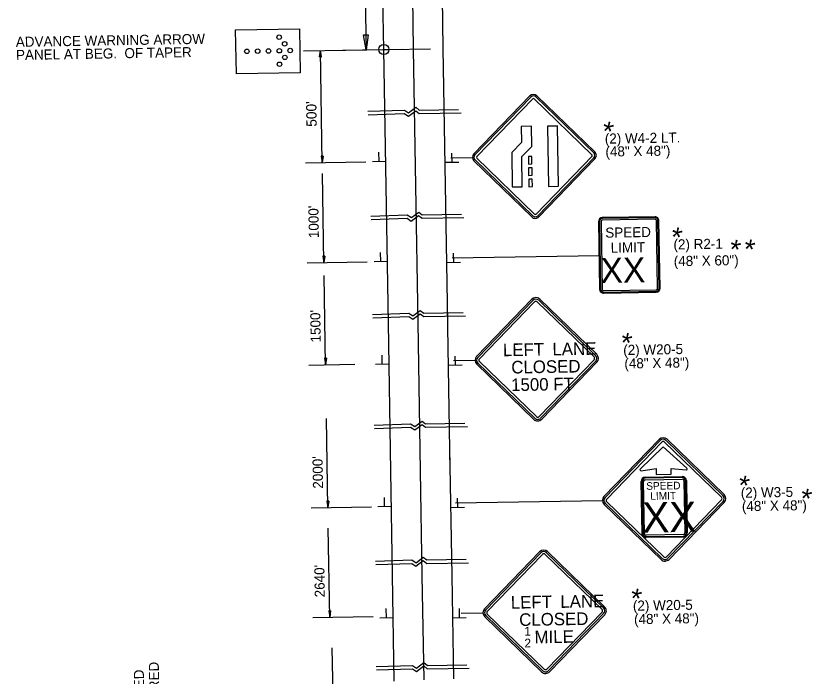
# Model space of a CAD drawing. Extents: x 1676063 to 1678026, y 228339 to 229904.
# Drawn here: x 1676063.3 to 1676538, y 228722.5 to 229116.1 of the extents above; entities that cross this region are included whole.
import ezdxf

# ---------------------------------------------------------------- set-up
doc = ezdxf.new("R2010")
doc.units = 0
for name, color, linetype in [('Default', 7, 'Continuous'), ('P_TC_Signs_Permanent', 7, 'Continuous'), ('P_TC_Signs_Temporary', 7, 'Continuous'), ('R_Annotation', 7, 'Continuous')]:
    doc.layers.add(name, color=color, linetype=linetype)

msp = doc.modelspace()

# ---------------------------------------------------------------- linework, layer by layer
at = {"layer": 'Default'}
for p, q in [((1676300.39, 229096.37), (1676288.34, 229823.3)), ((1676318.12, 229096.67), (1676306.07, 229823.59)), ((1676282.66, 229096.08), (1676270.61, 229823.01)), ((1676264.41, 229556.88), (1676272.05, 229095.9)), ((1676270.58, 229104.75), (1676273.23, 229104.79)), ((1676272.05, 229095.9), (1676270.58, 229104.75)), ((1676273.23, 229104.79), (1676272.05, 229095.9)), ((1676234.82, 229095.29), (1676310.43, 229096.54)), ((1676244.3, 229091.62), (1676244.81, 229095.45)), ((1676244.39, 229091.62), (1676244.82, 229094.81)), ((1676244.49, 229091.62), (1676244.83, 229094.16)), ((1676244.58, 229091.62), (1676244.84, 229093.52)), ((1676244.68, 229091.63), (1676244.85, 229092.87)), ((1676244.78, 229091.63), (1676244.86, 229092.23)), ((1676245.91, 229028.68), (1676244.81, 229095.45)), ((1676245.44, 229091.64), (1676244.81, 229095.45)), ((1676245.35, 229091.64), (1676244.82, 229094.81)), ((1676245.25, 229091.63), (1676244.83, 229094.16)), ((1676245.15, 229091.63), (1676244.84, 229093.52)), ((1676245.06, 229091.63), (1676244.85, 229092.87)), ((1676244.96, 229091.63), (1676244.86, 229092.23)), ((1676258.1, 229095.67), (1676294.01, 229096.27)), ((1676285.36, 228932.99), (1676282.66, 229096.08)), ((1676303.09, 228933.28), (1676300.39, 229096.37)), ((1676320.82, 228933.58), (1676318.12, 229096.67)), ((1676244.3, 229091.62), (1676245.44, 229091.64)), ((1676246.42, 229032.52), (1676245.28, 229032.5)), ((1676245.28, 229032.5), (1676245.91, 229028.68)), ((1676245.37, 229032.5), (1676245.9, 229029.32)), ((1676245.47, 229032.5), (1676245.89, 229029.98)), ((1676245.56, 229032.5), (1676245.88, 229030.61)), ((1676245.66, 229032.5), (1676245.87, 229031.26)), ((1676245.76, 229032.5), (1676245.86, 229031.9)), ((1676245.94, 229032.51), (1676245.86, 229031.9)), ((1676246.03, 229032.51), (1676245.87, 229031.26)), ((1676246.13, 229032.51), (1676245.88, 229030.61)), ((1676246.23, 229032.51), (1676245.89, 229029.98)), ((1676246.33, 229032.51), (1676245.9, 229029.32)), ((1676246.42, 229032.52), (1676245.91, 229028.68)), ((1676279.84, 229029.36), (1676279.75, 229034.81)), ((1676323.36, 229028.79), (1676323.26, 229034.24)), ((1676235.93, 229028.52), (1676271.84, 229029.11)), ((1676283.81, 229029.31), (1676275.83, 229029.18)), ((1676327.32, 229028.74), (1676319.35, 229028.61)), ((1676246.9, 228969.01), (1676246.02, 229022.23)), ((1676280.83, 228969.69), (1676280.74, 228975.13)), ((1676324.34, 228969.12), (1676324.25, 228974.57)), ((1676236.92, 228968.84), (1676272.82, 228969.44)), ((1676247.41, 228972.84), (1676246.26, 228972.82)), ((1676246.26, 228972.82), (1676246.9, 228969.01)), ((1676246.36, 228972.82), (1676246.89, 228969.65)), ((1676246.46, 228972.83), (1676246.88, 228970.3)), ((1676246.55, 228972.83), (1676246.87, 228970.94)), ((1676246.65, 228972.83), (1676246.86, 228971.59)), ((1676246.75, 228972.83), (1676246.85, 228972.23)), ((1676246.93, 228972.83), (1676246.85, 228972.23)), ((1676247.02, 228972.84), (1676246.86, 228971.59)), ((1676247.12, 228972.84), (1676246.87, 228970.94)), ((1676247.22, 228972.84), (1676246.88, 228970.3)), ((1676247.32, 228972.84), (1676246.89, 228969.65)), ((1676247.41, 228972.84), (1676246.9, 228969.01)), ((1676284.8, 228969.64), (1676276.82, 228969.5)), ((1676328.31, 228969.07), (1676320.34, 228968.94)), ((1676247.91, 228908.13), (1676247.03, 228961.36)), ((1676322.29, 228845.25), (1676320.67, 228942.93)), ((1676286.83, 228844.66), (1676285.36, 228932.99)), ((1676304.56, 228844.96), (1676303.09, 228933.28)), ((1676248.42, 228911.97), (1676247.27, 228911.95)), ((1676247.27, 228911.95), (1676247.91, 228908.13)), ((1676247.37, 228911.95), (1676247.9, 228908.77)), ((1676247.47, 228911.95), (1676247.89, 228909.43)), ((1676247.56, 228911.95), (1676247.88, 228910.07)), ((1676247.66, 228911.95), (1676247.87, 228910.71)), ((1676247.76, 228911.95), (1676247.86, 228911.35)), ((1676247.94, 228911.96), (1676247.86, 228911.35)), ((1676248.03, 228911.96), (1676247.87, 228910.71)), ((1676248.13, 228911.96), (1676247.88, 228910.07)), ((1676248.23, 228911.96), (1676247.89, 228909.43)), ((1676248.33, 228911.96), (1676247.9, 228908.77)), ((1676248.42, 228911.97), (1676247.91, 228908.13)), ((1676281.72, 228908.42), (1676281.63, 228913.87)), ((1676325.36, 228907.86), (1676325.27, 228913.3)), ((1676237.93, 228907.97), (1676265.31, 228908.42)), ((1676285.69, 228908.37), (1676277.71, 228908.24)), ((1676329.33, 228907.8), (1676321.35, 228907.67)), ((1676249.32, 228822.95), (1676248.44, 228876.17)), ((1676323.33, 228782.51), (1676322.07, 228858.33)), ((1676287.86, 228782.61), (1676286.83, 228844.66)), ((1676305.59, 228782.56), (1676304.56, 228844.96)), ((1676249.83, 228826.78), (1676248.69, 228826.76)), ((1676248.69, 228826.76), (1676249.32, 228822.95)), ((1676248.78, 228826.77), (1676249.31, 228823.59)), ((1676248.88, 228826.77), (1676249.3, 228824.25)), ((1676248.97, 228826.77), (1676249.29, 228824.88)), ((1676249.07, 228826.77), (1676249.28, 228825.53)), ((1676249.17, 228826.77), (1676249.27, 228826.17)), ((1676249.35, 228826.78), (1676249.27, 228826.17)), ((1676249.45, 228826.78), (1676249.28, 228825.53)), ((1676249.54, 228826.78), (1676249.29, 228824.88)), ((1676249.64, 228826.78), (1676249.3, 228824.25)), ((1676249.74, 228826.78), (1676249.31, 228823.59)), ((1676249.83, 228826.78), (1676249.32, 228822.95)), ((1676283.12, 228823.63), (1676283.03, 228829.07)), ((1676326.77, 228823.06), (1676326.68, 228828.51)), ((1676239.34, 228822.78), (1676275.25, 228823.38)), ((1676287.09, 228823.58), (1676279.11, 228823.44)), ((1676330.74, 228823.01), (1676322.76, 228822.88)), ((1676250.41, 228757.52), (1676249.53, 228810.74)), ((1676288.9, 228719.41), (1676287.86, 228782.61)), ((1676306.63, 228720.17), (1676305.59, 228782.56)), ((1676324.35, 228720.93), (1676323.33, 228782.51)), ((1676250.92, 228761.35), (1676249.77, 228761.33)), ((1676249.77, 228761.33), (1676250.41, 228757.52)), ((1676249.87, 228761.33), (1676250.4, 228758.15)), ((1676249.96, 228761.33), (1676250.39, 228758.81)), ((1676250.06, 228761.34), (1676250.38, 228759.45)), ((1676250.16, 228761.34), (1676250.37, 228760.1)), ((1676250.25, 228761.34), (1676250.35, 228760.74)), ((1676250.43, 228761.34), (1676250.35, 228760.74)), ((1676250.53, 228761.34), (1676250.37, 228760.1)), ((1676250.63, 228761.35), (1676250.38, 228759.45)), ((1676250.73, 228761.35), (1676250.39, 228758.81)), ((1676250.82, 228761.35), (1676250.4, 228758.15)), ((1676250.92, 228761.35), (1676250.41, 228757.52)), ((1676284.22, 228757.26), (1676284.13, 228762.71)), ((1676327.86, 228757.3), (1676327.77, 228762.74)), ((1676240.42, 228757.35), (1676276.33, 228757.95)), ((1676288.19, 228757.21), (1676280.21, 228757.08)), ((1676331.83, 228757.25), (1676323.85, 228757.11)), ((1676252.81, 228686.18), (1676251.93, 228739.41))]:
    msp.add_line(p, q, dxfattribs=at)
msp.add_lwpolyline([(1676232.72, 229082.1), (1676194.74, 229081.47), (1676194.31, 229107.74), (1676232.29, 229108.37)], close=True, dxfattribs=at)
for points in [[(1676273.17, 229059.22), (1676294.9, 229059.91), (1676297.39, 229058.3), (1676301.75, 229061.6), (1676303.82, 229059.93), (1676327.24, 229060.32)], [(1676273.4, 229057.19), (1676294.85, 229057.88), (1676297.34, 229056.26), (1676301.7, 229059.56), (1676303.77, 229057.9), (1676328.71, 229058.3)], [(1676274.85, 228996.77), (1676296.58, 228997.46), (1676299.07, 228995.85), (1676303.43, 228999.15), (1676305.5, 228997.48), (1676328.92, 228997.87)], [(1676275.08, 228994.74), (1676296.53, 228995.42), (1676299.02, 228993.81), (1676303.38, 228997.11), (1676305.45, 228995.44), (1676330.39, 228995.85)], [(1676275.82, 228938.17), (1676297.55, 228938.86), (1676300.04, 228937.25), (1676304.4, 228940.55), (1676306.47, 228938.88), (1676329.89, 228939.27)], [(1676276.05, 228936.14), (1676297.5, 228936.82), (1676299.99, 228935.21), (1676304.35, 228938.51), (1676306.42, 228936.84), (1676331.36, 228937.25)], [(1676276.92, 228872.18), (1676298.64, 228872.87), (1676301.13, 228871.26), (1676305.5, 228874.56), (1676307.56, 228872.89), (1676330.99, 228873.28)], [(1676277.15, 228870.15), (1676298.59, 228870.84), (1676301.08, 228869.22), (1676305.45, 228872.52), (1676307.51, 228870.86), (1676332.45, 228871.26)], [(1676277.62, 228791.03), (1676299.35, 228791.72), (1676301.84, 228790.1), (1676306.2, 228793.4), (1676308.27, 228791.74), (1676331.69, 228792.12)], [(1676277.85, 228789), (1676299.29, 228789.68), (1676301.79, 228788.07), (1676306.15, 228791.37), (1676308.21, 228789.7), (1676333.16, 228790.11)], [(1676277.99, 228728.19), (1676299.72, 228728.88), (1676302.21, 228727.26), (1676306.57, 228730.56), (1676308.64, 228728.9), (1676332.06, 228729.28)], [(1676278.22, 228726.16), (1676299.67, 228726.84), (1676302.16, 228725.22), (1676306.52, 228728.52), (1676308.59, 228726.86), (1676333.53, 228727.27)]]:
    msp.add_lwpolyline(points, dxfattribs=at)
for centre, radius in [((1676220.23, 229103.38), 1.34), ((1676223.52, 229099.41), 1.34), ((1676282.66, 229096.08), 3), ((1676201.01, 229095.01), 1.34), ((1676207.46, 229095.12), 1.34), ((1676213.91, 229095.22), 1.34), ((1676220.36, 229095.33), 1.34), ((1676223.65, 229091.36), 1.34), ((1676226.81, 229095.44), 1.34), ((1676220.49, 229087.28), 1.34)]:
    msp.add_circle(centre, radius, dxfattribs=at)
at = {"layer": 'P_TC_Signs_Permanent'}
for p, q in [((1676369.7, 229068.35), (1676336.33, 229033.85)), ((1676380.16, 229050.46), (1676386.16, 229050.56)), ((1676375.14, 228996.31), (1676408.51, 229030.81)), ((1676336.4, 229029.61), (1676370.9, 228996.24)), ((1676410.65, 228993.53), (1676411.32, 228953.03)), ((1676411.21, 228993.54), (1676411.88, 228953.04)), ((1676412.15, 228993.55), (1676412.82, 228953.06)), ((1676444.36, 228996.34), (1676412.86, 228995.82)), ((1676444.37, 228995.78), (1676412.87, 228995.25)), ((1676444.38, 228994.84), (1676412.89, 228994.32)), ((1676445.82, 228953.61), (1676445.15, 228994.1)), ((1676446.75, 228953.62), (1676446.08, 228994.12)), ((1676447.32, 228953.63), (1676446.65, 228994.13)), ((1676413.58, 228952.32), (1676445.08, 228952.84)), ((1676413.6, 228951.38), (1676445.1, 228951.91)), ((1676413.61, 228950.82), (1676445.1, 228951.34)), ((1676446.78, 228863.58), (1676413.93, 228829.62)), ((1676447.45, 228862.93), (1676414.6, 228828.97)), ((1676448.4, 228862.01), (1676415.54, 228828.05)), ((1676483.95, 228829.19), (1676449.99, 228862.04)), ((1676484.86, 228830.13), (1676450.9, 228862.98)), ((1676485.51, 228830.8), (1676451.55, 228863.66)), ((1676438.44, 228841.05), (1676460.63, 228841.41)), ((1676436.59, 228807.41), (1676436.08, 228838.61)), ((1676463.07, 228839.05), (1676463.59, 228807.86)), ((1676415.57, 228826.46), (1676449.53, 228793.61)), ((1676451.12, 228793.64), (1676483.97, 228827.6)), ((1676452.06, 228792.72), (1676484.92, 228826.68)), ((1676414.01, 228824.84), (1676447.97, 228791.99)), ((1676414.66, 228825.52), (1676448.62, 228792.67)), ((1676452.74, 228792.07), (1676485.59, 228826.03)), ((1676461.23, 228805.42), (1676439.03, 228805.05))]:
    msp.add_line(p, q, dxfattribs=at)
for points in [[(1676408.44, 229035.05), (1676391.19, 229051.74), (1676373.94, 229068.42)], [(1676336.97, 229033.23), (1676370.35, 229067.73)], [(1676371.43, 229066.68), (1676338.05, 229032.19)], [(1676406.77, 229033.32), (1676372.27, 229066.7)], [(1676373.32, 229067.78), (1676407.82, 229034.4)], [(1676338.07, 229031.34), (1676372.56, 228997.96)], [(1676373.41, 228997.98), (1676406.79, 229032.48)], [(1676407.86, 229031.43), (1676374.49, 228996.93)], [(1676371.52, 228996.88), (1676337.02, 229030.26)], [(1676463.3, 228846.37), (1676449.2, 228859.23), (1676435.54, 228845.91)], [(1676436.01, 228844.95), (1676444.95, 228846.22), (1676445.01, 228842.65), (1676454.01, 228842.8), (1676453.95, 228846.36), (1676462.86, 228845.4)], [(1676460.64, 228840.81), (1676449.55, 228840.63), (1676438.45, 228840.45)], [(1676436.68, 228838.62), (1676437.19, 228807.42)], [(1676438.09, 228807.44), (1676437.58, 228838.63)], [(1676438.46, 228839.55), (1676449.56, 228839.73), (1676460.66, 228839.91)], [(1676461.57, 228839.03), (1676462.09, 228807.83)], [(1676462.99, 228807.85), (1676462.47, 228839.04)], [(1676461.21, 228806.92), (1676439.01, 228806.55)], [(1676439.02, 228805.65), (1676461.22, 228806.02)]]:
    msp.add_lwpolyline(points, dxfattribs=at)
for points in [[(1676359.22, 229014.11), (1676365.22, 229014.21), (1676364.92, 229032.21), (1676370.82, 229038.3), (1676370.62, 229050.3), (1676364.62, 229050.2), (1676364.78, 229040.69), (1676358.88, 229034.59)], [(1676380.76, 229014.47), (1676386.76, 229014.57), (1676386.16, 229050.56), (1676380.16, 229050.46)], [(1676368.89, 229027.77), (1676370.99, 229027.81), (1676370.92, 229032.31), (1676368.82, 229032.27)], [(1676369.01, 229021.02), (1676371.11, 229021.06), (1676371.03, 229025.56), (1676368.93, 229025.52)], [(1676369.12, 229014.27), (1676371.22, 229014.31), (1676371.14, 229018.81), (1676369.04, 229018.77)]]:
    msp.add_lwpolyline(points, close=True, dxfattribs=at)
for centre, radius, start, end in [((1676371.86, 229066.27), 3, 45.9497, 135.9497), ((1676371.86, 229066.27), 2.1, 45.9497, 135.9497), ((1676371.86, 229066.27), 0.6, 45.9497, 135.9497), ((1676338.48, 229031.77), 3, 135.9497, 225.9497), ((1676338.48, 229031.77), 2.1, 135.9497, 225.9497), ((1676338.48, 229031.77), 0.6, 135.9497, 225.9497), ((1676406.36, 229032.89), 0.6, 315.9497, 45.9497), ((1676406.36, 229032.89), 2.1, 315.9497, 45.9497), ((1676406.36, 229032.89), 3, 315.9497, 45.9497), ((1676372.98, 228998.39), 0.6, 225.9497, 315.9497), ((1676372.98, 228998.39), 3, 225.9497, 315.9497), ((1676372.98, 228998.39), 2.1, 225.9497, 315.9497), ((1676412.9, 228993.57), 2.25, 90.9497, 180.9497), ((1676412.9, 228993.57), 1.69, 90.9497, 180.9497), ((1676412.9, 228993.57), 0.75, 90.9497, 180.9497), ((1676444.4, 228994.09), 2.25, 0.9497, 90.9497), ((1676444.4, 228994.09), 1.69, 0.9497, 90.9497), ((1676444.4, 228994.09), 0.75, 0.9497, 90.9497), ((1676413.57, 228953.07), 2.25, 180.9497, 270.9497), ((1676413.57, 228953.07), 1.69, 180.9497, 270.9497), ((1676413.57, 228953.07), 0.75, 180.9497, 270.9497), ((1676445.07, 228953.59), 0.75, 270.9497, 0.9497), ((1676445.07, 228953.59), 2.25, 270.9497, 0.9497), ((1676445.07, 228953.59), 1.69, 270.9497, 0.9497), ((1676449.2, 228861.23), 3.38, 45.9497, 135.9497), ((1676449.2, 228861.23), 2.44, 45.9497, 135.9497), ((1676449.2, 228861.23), 1.13, 45.9497, 135.9497), ((1676435.93, 228845.51), 0.563, 134.2614, 278.0747), ((1676462.92, 228845.96), 0.563, 263.8247, 47.6381), ((1676438.48, 228838.65), 2.4, 90.9497, 180.9497), ((1676460.67, 228839.01), 2.4, 0.9497, 90.9497), ((1676460.67, 228839.01), 1.8, 0.9497, 90.9497), ((1676438.48, 228838.65), 1.8, 90.9497, 180.9497), ((1676438.48, 228838.65), 0.9, 90.9497, 180.9497), ((1676460.67, 228839.01), 0.9, 0.9497, 90.9497), ((1676416.35, 228827.27), 3.38, 135.9497, 225.9497), ((1676416.35, 228827.27), 2.44, 135.9497, 225.9497), ((1676416.35, 228827.27), 1.13, 135.9497, 225.9497), ((1676483.16, 228828.38), 1.13, 315.9497, 45.9497), ((1676483.16, 228828.38), 2.44, 315.9497, 45.9497), ((1676483.16, 228828.38), 3.38, 315.9497, 45.9497), ((1676438.99, 228807.45), 2.4, 180.9497, 270.9497), ((1676438.99, 228807.45), 1.8, 180.9497, 270.9497), ((1676438.99, 228807.45), 0.9, 180.9497, 270.9497), ((1676461.19, 228807.82), 0.9, 270.9497, 0.9497), ((1676461.19, 228807.82), 1.8, 270.9497, 0.9497), ((1676461.19, 228807.82), 2.4, 270.9497, 0.9497), ((1676450.31, 228794.42), 1.13, 225.9497, 315.9497), ((1676450.31, 228794.42), 3.38, 225.9497, 315.9497), ((1676450.31, 228794.42), 2.44, 225.9497, 315.9497)]:
    msp.add_arc(centre, radius, start, end, dxfattribs=at)
at = {"layer": 'P_TC_Signs_Temporary'}
for p, q in [((1676338.01, 228913.18), (1676370.86, 228947.14)), ((1676338.68, 228912.52), (1676371.53, 228946.48)), ((1676339.62, 228911.61), (1676372.48, 228945.57)), ((1676374.07, 228945.6), (1676408.03, 228912.75)), ((1676374.98, 228946.54), (1676408.94, 228913.69)), ((1676375.63, 228947.21), (1676409.59, 228914.36)), ((1676372.04, 228875.55), (1676338.08, 228908.4)), ((1676372.7, 228876.22), (1676338.74, 228909.08)), ((1676373.61, 228877.17), (1676339.65, 228910.02)), ((1676408.05, 228911.15), (1676375.2, 228877.19)), ((1676409, 228910.24), (1676376.14, 228876.28)), ((1676409.67, 228909.59), (1676376.82, 228875.63)), ((1676342.72, 228762.66), (1676375.57, 228796.62)), ((1676343.39, 228762), (1676376.24, 228795.96)), ((1676344.33, 228761.09), (1676377.19, 228795.05)), ((1676378.78, 228795.08), (1676412.74, 228762.22)), ((1676379.69, 228796.02), (1676413.65, 228763.17)), ((1676380.34, 228796.69), (1676414.3, 228763.84)), ((1676412.76, 228760.63), (1676379.91, 228726.67)), ((1676376.75, 228725.03), (1676342.79, 228757.88)), ((1676377.41, 228725.7), (1676343.45, 228758.56)), ((1676378.32, 228726.65), (1676344.36, 228759.5)), ((1676413.71, 228759.72), (1676380.85, 228725.76)), ((1676414.38, 228759.07), (1676381.53, 228725.11))]:
    msp.add_line(p, q, dxfattribs=at)
for centre, radius, start, end in [((1676373.28, 228944.79), 3.38, 45.9497, 135.9497), ((1676373.28, 228944.79), 2.44, 45.9497, 135.9497), ((1676373.28, 228944.79), 1.13, 45.9497, 135.9497), ((1676340.43, 228910.83), 3.38, 135.9497, 225.9497), ((1676340.43, 228910.83), 2.44, 135.9497, 225.9497), ((1676407.24, 228911.94), 1.12, 315.9497, 45.9497), ((1676407.24, 228911.94), 2.44, 315.9497, 45.9497), ((1676407.24, 228911.94), 3.38, 315.9497, 45.9497), ((1676340.43, 228910.83), 1.12, 135.9497, 225.9497), ((1676374.39, 228877.98), 3.38, 225.9497, 315.9497), ((1676374.39, 228877.98), 2.44, 225.9497, 315.9497), ((1676374.39, 228877.98), 1.13, 225.9497, 315.9497), ((1676377.99, 228794.27), 3.38, 45.9497, 135.9497), ((1676377.99, 228794.27), 2.44, 45.9497, 135.9497), ((1676377.99, 228794.27), 1.13, 45.9497, 135.9497), ((1676345.14, 228760.31), 3.38, 135.9497, 225.9497), ((1676345.14, 228760.31), 2.44, 135.9497, 225.9497), ((1676345.14, 228760.31), 1.12, 135.9497, 225.9497), ((1676411.95, 228761.42), 1.12, 315.9497, 45.9497), ((1676411.95, 228761.42), 2.44, 315.9497, 45.9497), ((1676411.95, 228761.42), 3.38, 315.9497, 45.9497), ((1676379.1, 228727.46), 1.13, 225.9497, 315.9497), ((1676379.1, 228727.46), 3.38, 225.9497, 315.9497), ((1676379.1, 228727.46), 2.44, 225.9497, 315.9497)]:
    msp.add_arc(centre, radius, start, end, dxfattribs=at)
at = {"layer": 'R_Annotation'}
for p, q in [((1676322.56, 229031.5), (1676335.48, 229031.72)), ((1676323.33, 228971.83), (1676410.99, 228973.28)), ((1676324.13, 228910.56), (1676337.06, 228910.77)), ((1676325.32, 228825.76), (1676412.98, 228827.21)), ((1676328.84, 228760.04), (1676341.77, 228760.25))]:
    msp.add_line(p, q, dxfattribs=at)

# ---------------------------------------------------------------- texts
at = {"layer": 'Default'}
for s, height, p in [("500'", 6.12, (1676242.65, 229050.05)), ("1000'", 6, (1676243.94, 228983.65)), ("1500'", 6, (1676245.06, 228921.46)), ("2000'", 6, (1676246.41, 228834.29)), ("2640'", 6, (1676247.49, 228769.51))]:
    msp.add_text(s, height=height, rotation=90.9497, dxfattribs=at).set_placement(p)
at = {"layer": 'P_TC_Signs_Permanent'}
for s, height, p in [('SPEED', 6, (1676414.74, 228983.85)), ('LIMIT', 6, (1676417.98, 228974.9)), ('XX', 15, (1676411.96, 228956.8)), ('SPEED', 4.5, (1676439.16, 228833.56)), ('LIMIT', 4.5, (1676441.57, 228827.6)), ('XX', 18, (1676436.95, 228808.02))]:
    msp.add_text(s, height=height, rotation=0.9497, dxfattribs=at).set_placement(p)
at = {"layer": 'P_TC_Signs_Temporary'}
for s, height, p in [('LEFT\u2002LANE', 7.5, (1676353.72, 228913.18)), ('CLOSED', 7.5, (1676358.72, 228902.88)), ('1500 FT', 7.5, (1676358.63, 228892.38)), ('LEFT\u2002LANE', 7.5, (1676358.43, 228762.66)), ('CLOSED', 7.5, (1676363.43, 228752.36)), ('1', 5.25, (1676366.43, 228746.53)), (' MILE', 7.5, (1676369.77, 228741.96)), ('2', 5.25, (1676366.55, 228739.54))]:
    msp.add_text(s, height=height, rotation=0.9497, dxfattribs=at).set_placement(p)
at = {"layer": 'R_Annotation'}
for s, height, rotation, p in [('ADVANCE WARNING ARROW', 6, 0.9497, (1676063.28, 229097.59)), ('PANEL AT BEG.  OF TAPER', 6, 0.9497, (1676063.41, 229089.8)), ('*', 12, 135.9497, (1676424.98, 229054.14)), ('(2) W4-2 LT.', 6, 0.9497, (1676414.46, 229039.92)), ('(48" X 48")', 6, 0.9497, (1676414.84, 229032.2)), ('*', 12, 135.9497, (1676465.93, 228991.07)), ('(2) R2-1', 6, 0.9497, (1676455.4, 228976.85)), ('*', 12, 135.9497, (1676500.81, 228983.69)), ('*', 12, 135.9497, (1676509.35, 228983.83)), ('(48" X 60")', 6, 0.9497, (1676455.57, 228966.88)), ('*', 12, 135.9497, (1676435.96, 228928.13)), ('(2) W20-5', 6, 0.9497, (1676425.44, 228913.92)), ('(48" X 48")', 6, 0.9497, (1676426.12, 228905.87)), ('*', 12, 135.9497, (1676506.05, 228843.04)), ('(2) W3-5', 6, 0.9497, (1676495.53, 228828.82)), ('*', 12, 135.9497, (1676543.22, 228835.25)), ('(48" X 48")', 6, 0.9497, (1676496.2, 228820.78)), ('*', 12, 135.9497, (1676441.75, 228775.67)), ('(2) W20-5', 6, 0.9497, (1676431.22, 228761.46)), ('(48" X 48")', 6, 0.9497, (1676431.9, 228753.41)), ('SOUTHBOUND UNDIVIDED HIGHWAY ONE (1) SIGN REQUIRED', 6, 90.9497, (1676152.5, 228489.04)), ('NORTHBOUND DIVIDED HIGHWAY TWO (2) SIGNS REQUIRED ', 6, 90.9497, (1676143.5, 228488.89))]:
    msp.add_text(s, height=height, rotation=rotation, dxfattribs=at).set_placement(p)

doc.saveas('drawing.dxf')
